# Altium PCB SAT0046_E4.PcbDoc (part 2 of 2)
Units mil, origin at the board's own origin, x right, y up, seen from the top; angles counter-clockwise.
Board outline 1588 x 1588 mil, 4 copper layers (Top Layer, GND, Inner 1, Bottom Layer); 110 components, 70 nets, 285 pads, 141 vias.
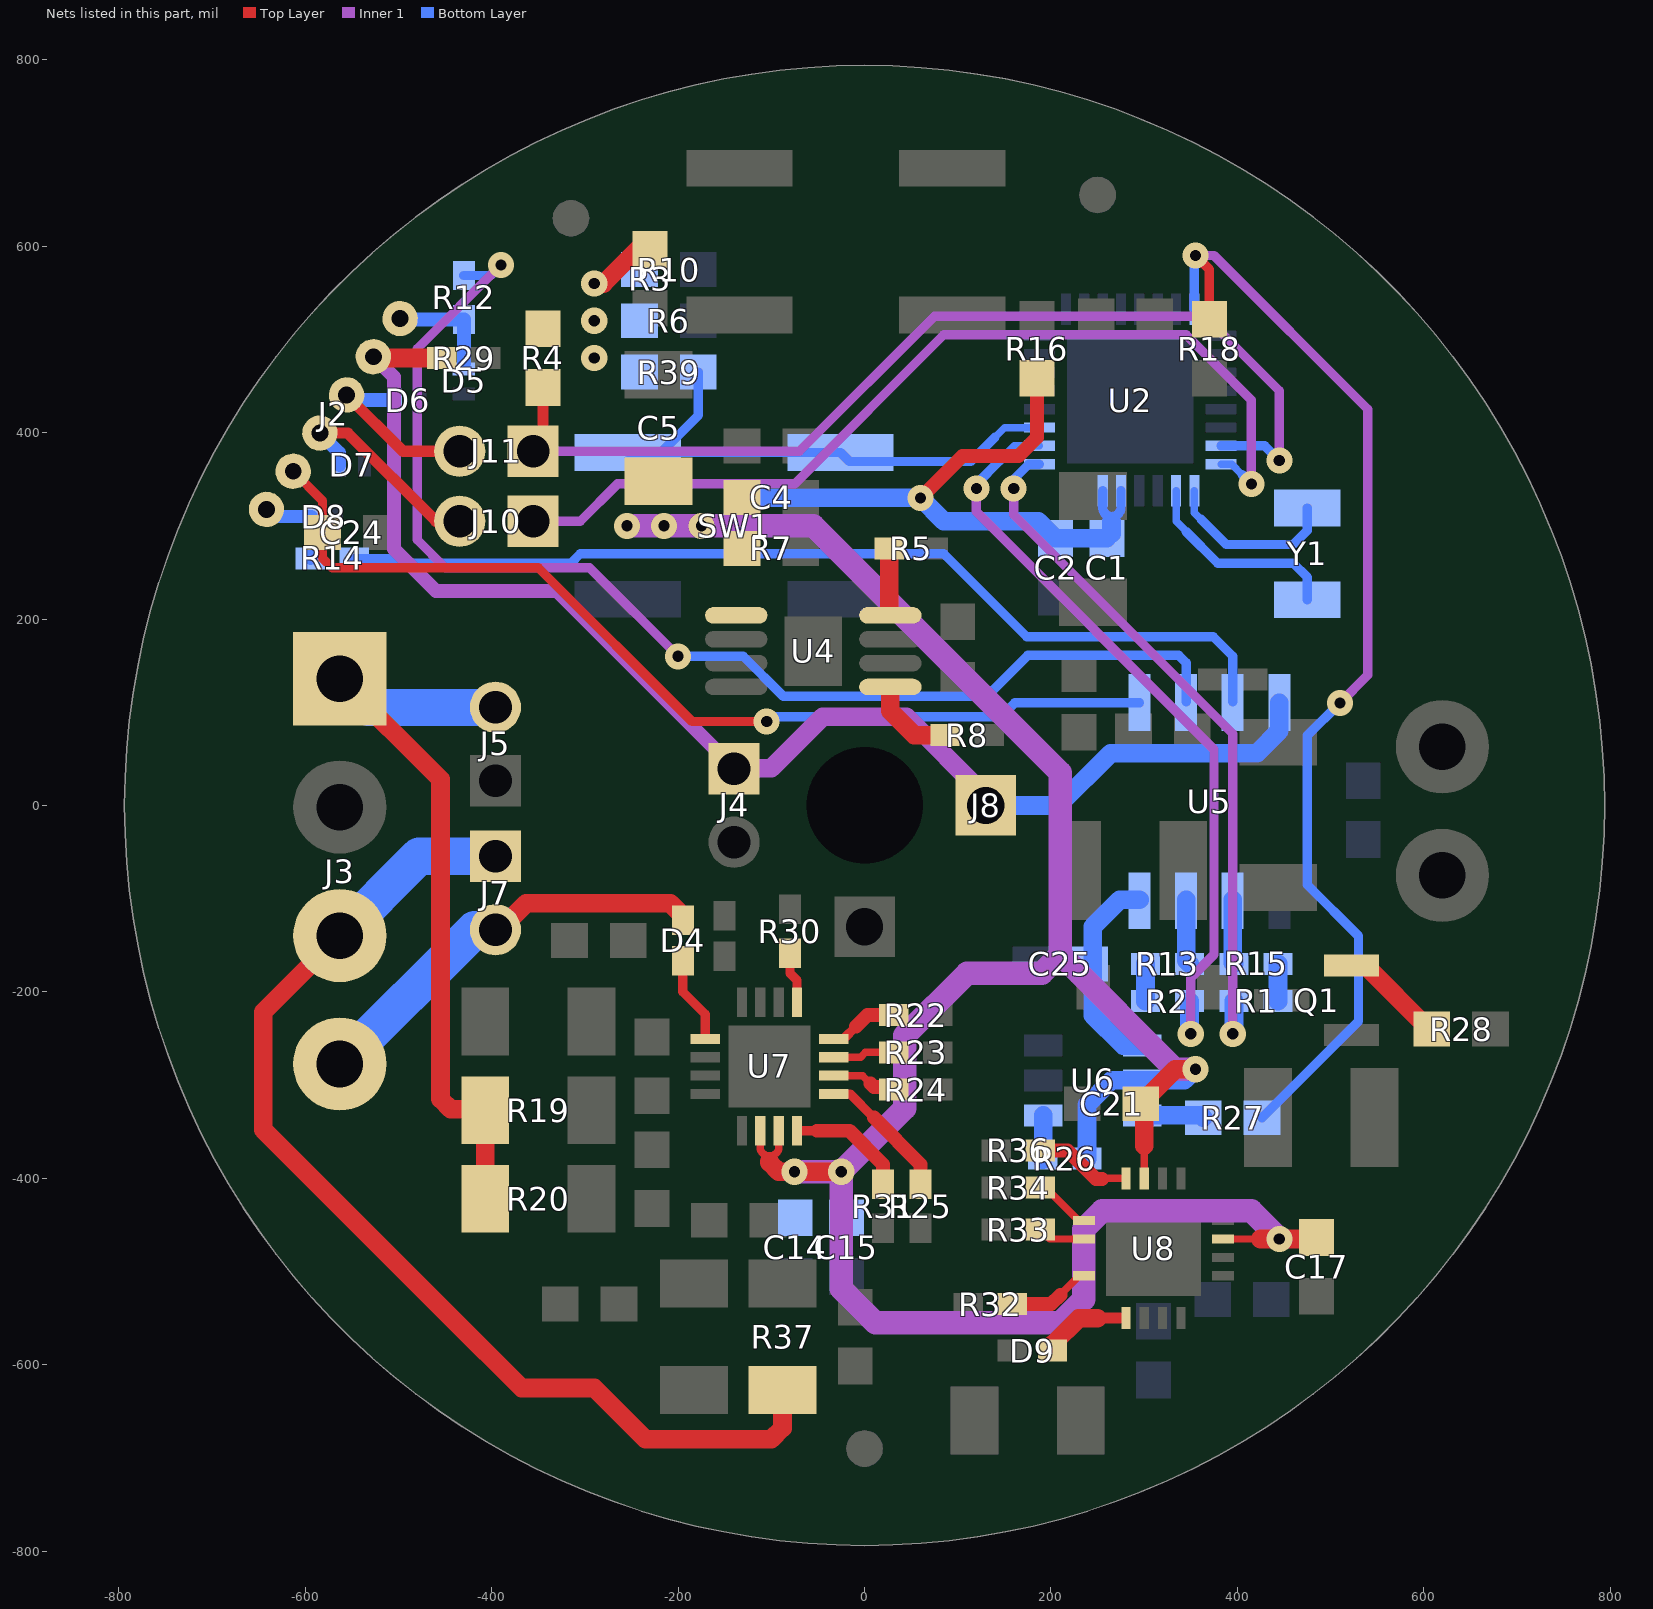
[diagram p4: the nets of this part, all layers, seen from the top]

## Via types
v1: diameter 28, hole 12, Top Layer to Bottom Layer, tented both sides, 120 vias
v2: diameter 23.62, hole 11.81, Top Layer to Bottom Layer, tented both sides, 16 vias
v3: diameter 19.68, hole 7.87, Top Layer to Bottom Layer, tented both sides, 5 vias

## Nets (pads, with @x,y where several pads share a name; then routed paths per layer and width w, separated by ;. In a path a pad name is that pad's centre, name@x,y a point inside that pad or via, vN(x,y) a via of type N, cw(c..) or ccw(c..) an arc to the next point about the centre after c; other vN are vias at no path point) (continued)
NetD4_1: D4.1 J3.4 J7.2 | length 444.9
  Top Layer w20: J7.2@-396,-133.37 -391.46,-133.37 -363.09,-105 -208.35,-105 D4.1@-195,-118.35
  Bottom Layer w40: J3.4@-563,-277.39 -562.39,-277.39 -418.37,-133.37 J7.2@-396,-133.37
NetD4_2: D4.2 U7.5 | length 97.3
  Top Layer w10: D4.2@-195,-161.65 -195,-200 -170.9,-224.1 U7.5@-170.9,-249
NetD6_1: D6.1 J2.4 J11.2 | length 194.6
  Top Layer w12: J2.4@-555.66,440.48 -495.18,380 J11.2@-434.37,380
  Bottom Layer w15: J2.4@-555.66,440.48 -550.18,435 D6.1@-509.68,435
NetD7_1: D7.1 J2.3 J10.2 | length 232.3
  Top Layer w12: J2.3@-584.34,399.52 -554.52,399.52 -460,305 J10.2@-434.37,305
  Bottom Layer w14: J2.3@-584.34,399.52 -563.39,378.57 D7.1@-563.39,365
NetD9_2: D9.2 U8.9 | length 91.8
  Top Layer w12: 250,-550 250.2,-549.8 275,-549.8
  Top Layer w20: D9.2@201.65,-585 201.65,-578.35 230,-550 250,-550
NetJ3_1: J3.1 J5.2 R19.1 R20.2 | length 822
  Top Layer w20: J3.1@-563,136 -455,28 -455,-315 -444,-326 R19.1@-408.09,-326 ; R20.2@-407.09,-422 R19.1@-407.09,-327
  Bottom Layer w40: J3.1@-563,136 -532,105 J5.2@-396,105
NetJ3_3: J3.3 J7.1 R37.1 | length 1185
  Top Layer w20: J3.3@-563,-139.59 -645,-221.59 -645,-348 -443,-550 ; -442.96,-550 -367.96,-625 -290,-625 -235,-680 -100,-680 -88,-668 R37.1@-88,-627.09
  Bottom Layer w40: J3.3@-563,-139.59 -478.04,-54.63 J7.1@-396,-54.63
NetJ10_1: J10.1 U2.24 | length 1013.8
  Inner 1 w10: J10.1@-355.63,305 -305,305 -265,345 -75,345 85,505 345,505 415,435 v1(415,345)
  Bottom Layer w8: U2.24@382.44,366.1 393.9,366.1 405,355
  Bottom Layer w10: 405,355 v1(415,345)
NetJ11_1: J11.1 R4.1 U2.23 | length 1110.8
  Top Layer w12: J11.1@-355.63,380 -345,390.63 R4.1@-345,448.5
  Inner 1 w10: J11.1@-355.63,380 -70,380 75,525 365,525 445,445 v1(445,370)
  Bottom Layer w10: U2.23@382.44,385.79 429.21,385.79 v1(445,370)
NetQ1_2: Q1.2 R28.2 | length 111.5
  Top Layer w20: Q1.2@522.4,-171.6 537.17,-171.6 R28.2@605.57,-240
NetR1_1: R1.1 U2.1 | length 762.1
  Inner 1 w10: v1(160,340) 160,312 395,77 v1(395,-245)
  Bottom Layer w10: v1(160,340) 160,350 176.1,366.1 U2.1@187.56,366.1
  Bottom Layer w20: v1(395,-245) 396.38,-243.62 R1.1@396.38,-210
NetR2_1: R2.1 U2.2 | length 826
  Inner 1 w10: v1(120,340) 120,315 375,60 375,-160 350,-185 v1(350,-245)
  Bottom Layer w8: 145,370 160.79,385.79 U2.2@187.56,385.79
  Bottom Layer w10: v1(120,340) 120,345 145,370
  Bottom Layer w20: R2.1@348.62,-210 348.62,-243.62 v1(350,-245)
NetR5_1: R5.1 U4.8 | length 65
  Top Layer w20: U4.8@26.38,210.5 R5.1@26.38,275.5
NetR8_2: R8.2 U4.5 | length 88.6
  Top Layer w20: U4.5@27.68,120.5 27.68,101.32 53.5,75.5 R8.2@86.38,75.5
NetR12_2: R12.2 U5.2 | length 1334.8
  Inner 1 w10: v1(-390,580) -480,490 -480,285 -450,255 -295,255 v1(-200,160)
  Bottom Layer w10: R12.2@-430,568.62 -401.38,568.62 v1(-390,580) ; v1(-200,160) -130,160 -87,117 131,117 175,161 337,161 345,153 U5.2@345,111.3
NetR13_1: R13.1 U5.7 | length 70.2
  Bottom Layer w20: U5.7@345,-101.3 345,-166.38 R13.1@348.62,-170
NetR14_2: R14.2 U5.3 | length 1042.9
  Bottom Layer w10: R14.2@-547.38,265 -503,265 -498,260 -315,260 -305,270 85,270 174,181 374,181 395,160 U5.3@395,111.3
NetR15_1: R15.1 U5.6 | length 69.3
  Bottom Layer w20: U5.6@395,-101.3 395,-168.62 R15.1@396.38,-170
NetR22_1: R22.1 U7.16 | length 75
  Top Layer w10: U7.16@-33.1,-250.47 -22.47,-250.47 -9,-237
  Top Layer w15: -9,-237 3,-225 R22.1@31.38,-225
NetR23_1: R23.1 U7.15 | length 66.6
  Top Layer w8: U7.15@-33.1,-270.16 -4.16,-270.16 1,-265 R23.1@31.38,-265
NetR24_1: R24.1 U7.14 | length 70.8
  Top Layer w8: U7.14@-33.1,-289.84 -2.16,-289.84 6.5,-298.5
  Top Layer w15: 6.5,-298.5 10,-302 28.38,-302 R24.1@31.38,-305
NetR25_1: R25.1 U7.13 | length 145.7
  Top Layer w10: U7.13@-33.1,-309.53 -15.47,-309.53 10,-335
  Top Layer w15: 10,-335 60,-385 R25.1@60,-406.38
NetR26_1: R26.1 U6.1 | length 47.8
  Bottom Layer w20: R26.1@191.38,-380 R26.1@191.38,-379 191.85,-378.53 U6.1@191.85,-332.4
NetR27_1: R27.1 U6.6 | length 66.4
  Bottom Layer w20: U6.6@298.15,-332.4 360.91,-332.4 R27.1@363.5,-335
NetR30_2: R30.2 U7.1 | length 55.6
  Top Layer w10: R30.2@-80,-158.62 -80,-180 -72.47,-187.53 U7.1@-72.47,-211.1
NetR31_2: R31.2 U7.12 | length 128.8
  Top Layer w10: U7.12@-72.47,-348.9 -72.37,-349 -51,-349
  Top Layer w15: -51,-349 -16,-349 20,-385 R31.2@20,-406.38
NetR32_2: R32.2 U8.8 | length 89.2
  Top Layer w8: 210,-525 230.47,-504.53 U8.8@235.2,-504.53
  Top Layer w15: R32.2@158.62,-535 200,-535 210,-525
NetR33_2: R33.2 U8.6 | length 50.8
  Top Layer w8: R33.2@188.62,-455 198.78,-465.16 U8.6@235.2,-465.16
NetR34_2: R34.2 U8.5 | length 61.3
  Top Layer w8: R34.2@188.62,-410 194.21,-410 229.68,-445.47 U8.5@235.2,-445.47
NetR36_1: R36.1 U8.4 | length 104.7
  Top Layer w8: 255,-400.65 255.46,-400.2 U8.4@280.47,-400.2
  Top Layer w15: R36.1@188.62,-370 217.81,-370 248.46,-400.65 255,-400.65
NetU2_25: U2.25 Y1.2 | length 189.1
  Bottom Layer w8: U2.25@353.9,337.56 353.9,314.1 360.93,307.07
  Bottom Layer w10: 360.93,307.07 388,280 460,280 475,295 Y1.2@475,319.21
NetU2_26: U2.26 Y1.1 | length 222.5
  Bottom Layer w8: U2.26@334.21,337.56 334.21,304.79 345,294
  Bottom Layer w10: 345,294 379,260 460,260 475,245 Y1.1@475,220.79
PC_GND: J2.5 J4.1 J8.1 R29.2 U5.4 | length 1468.3
  Top Layer w20: J2.5@-526.98,481.44 -525.55,480 R29.2@-453.62,480
  Inner 1 w15: J2.5@-526.98,481.44 -505,459.45 -505,275 -460,230 -330,230 -145,45 J4.1@-140,45
  Inner 1 w20: J4.1@-140,45 -135,40 -100,40 -45,95 45,95 130,10 J8.1@130,0
  Bottom Layer w20: J8.1@130,0 208,0 264,56 421,56 445,80 U5.4@445,110.3
UART_PC_RX: D5.1 J2.6 R12.1 | length 115.4
  Bottom Layer w15: J2.6@-498.3,522.39 -497.29,521.38 R12.1@-430,521.38 D5.1@-430,474.68
UART_PC_TX: D8.1 J2.1 R14.1 | length 97
  Bottom Layer w14: J2.1@-641.7,317.61 -634.09,310 D8.1@-593.39,310 -593.39,266.24 R14.1@-594.62,265
UART_RX: R1.2 R15.2 | length 40
  Bottom Layer w20: R1.2@443.62,-210 R15.2@443.62,-170
UART_TX: R2.2 R13.2 | length 40
  Bottom Layer w20: R2.2@301.38,-210 R13.2@301.38,-170
USR_UART_INTERRUPT: R39.1 SW1.1 SW1.4 U2.3 | length 563.6
  Bottom Layer w8: 140,395 150.47,405.47 U2.3@187.56,405.47
  Bottom Layer w10: SW1.4@-254.17,378.74 SW1.4@-218.27,378.74 ; R39.1@-178.5,465 -178.5,418.5 SW1.4@-218.27,378.74 ; 140,395 114,369 -16.09,369 SW1.1@-25.83,378.74 SW1.4@-218.27,378.74
VCC: C1.1 C2.2 C4.2 C5.1 C14.1 C15.1 C17.1 C21.1 R3.2 R4.2 R6.2 R7.2 R10.2 R16.2 R26.2 R39.2 U2.29 U2.30 U4.1 U6.5 U7.10 U7.11 U8.3 U8.15 | length 3614.2
  Top Layer w8: -111.91,-368.87 ccw(c-102,-365.55) -92.09,-368.87 ; -111.84,-368.84 U7.10@-111.84,-348.9 ; -92.16,-368.84 U7.11@-92.16,-348.9 ; 300,-365 300.16,-365.16 U8.3@300.16,-400.2 ; U8.15@384.8,-465.16 424.84,-465.16
  Top Layer w9: v1(355,-283) v1@355.16,-283.16
  Top Layer w15: v1(60,330) 105,375 165,375 185,395 R16.2@185,458.5
  Top Layer w20: v1(-290,560) -280,560 -243.5,596.5 R3.2@-230,596.5 ; -102,-382 -102,-383 -92,-393 v1(-75,-393) v1(-25,-393) ; 300,-365 300,-323.5 C21.1@296.5,-320 333.5,-283 v1(355,-283) ; 424.84,-465.16 C17.1@483.35,-465.16
  Inner 1 w25: v1(-255,300) -55,300 210,35 210,-160 190,-180 110,-180 43.19,-246.81 43.19,-324.81 v1(-25,-393) ; v1(-75,-393) v1(-25,-393) ; 212.5,-162.5 333,-283 v1(355,-283) ; v1(445,-465.16) 414.84,-435 255,-435 235.2,-454.8 235.2,-529.8 210,-555 11.65,-555 -25,-518.35 v1(-25,-393)
  Bottom Layer w10: U2.30@255.47,337.56 255.47,320.47 ccw(c265.31,319.85) 275.16,320.16 U2.29@275.16,337.56
  Bottom Layer w20: v1(-255,300) -150,300 -120,330 v1(60,330) 85,305 186.5,305 C2.2@205,286.5 C1.1@260,286.5 ; R26.2@238.62,-379 238.62,-321.38 265,-295 U6.5@298.15,-295 343,-295 v1(355,-283) ; C1.1@265,291.5 C1.1@265,305
  other v1: -215,300 -175,300 -290,480 -290,520
VCC_ISO_UART: C25.1 U5.8 U6.4 | length 223.5
  Bottom Layer w20: U5.8@295,-101.3 273.7,-101.3 245,-130 245,-225 277.6,-257.6 U6.4@298.15,-257.6
VCC_ISO_UART_EN: R18.2 R27.2 U2.16 | length 1238.7
  Top Layer w10: v1(355,590) 370,575 R18.2@370,521.5
  Inner 1 w10: v1(355,590) 375,590 540,425 540,140 v1(510,110)
  Bottom Layer w10: U2.16@353.9,532.44 353.9,588.9 v1(355,590) ; R27.2@426.5,-335 530,-231.5 530,-140 475,-85 475,75 v1(510,110)
VCC_USB: C24.1 J2.2 U5.1 | length 1063.8
  Top Layer w10: J2.2@-613.02,358.56 -581.5,327.04 -581.5,265.3 -571.2,255 -350,255 -185,90 v1(-105,90)
  Bottom Layer w10: v1(-105,90) -100,95 146,95 161.3,110.3 U5.1@295,110.3
pads on no net: FID1.1 FID2.1 FID3.1 FID4.1 FID5.1 FID6.1 H1.0 H2.0 H3.0 U2.7 U2.8 U2.11 U2.12 U2.13 U2.14 U2.18 U2.19 U2.20 U2.31 U2.32 U4.3 U4.7 U6.3

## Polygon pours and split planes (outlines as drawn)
GND on Top Layer "TOP - GND" (solid, pour order 13): -675,-379 -675,-200 -635,-160 -635,206 -491,206 -445,160 -375,160 -310,95 -310,30 -115,-165 -115,-210 -25,-210 20,-255 150,-255 180,-225 180,-55 65,-55 20,-10 -200,-10 -200,65 -365,230 -730,230 -730,205 -770,165 -770,-145 -745,-170 -745,-250 -710,-285 -710,-350 -681,-379
GND on Top Layer "TOP - GND" (solid, pour order 15): 630,425 410,425 410,585 300,695 225,695 100,570 -104,570 -204,670 -350,670 -440,580 -495,580 -495,590 -405,680 -345,680 -290,735 -195,735 -155,775 160,775 180,755 240,755 285,710 355,710 458,607 503,607 630,480
GND on Top Layer "TOP - GND" (solid, pour order 11): -305,-700 -280,-700 -270,-710 -65,-710 -40,-735 25,-735 50,-710 50,-655 30,-635 30,-565 50,-545 155,-545 195,-585 195,-650 395,-650 325,-720 250,-720 210,-760 -200,-760 -230,-730 -275,-730
GND on Bottom Layer "BOTTOM - GND" (solid, pour order 17): -735,230 -365,230 -289,154 -244,154 -200,110 -200,-10 15,-10 60,-55 225,-55 225,-105 200,-130 160,-130 150,-140 150,-155 0,-305 0,-610 40,-610 40,-635 75,-635 75,-715 340,-715 340,-725 305,-725 275,-755 -205,-755 -230,-730 -295,-730 -355,-670 -415,-670 -660,-425 -660,-370 -720,-310 -720,-245 -760,-205 -760,155 -755,160 -635,160 -635,-310 -595,-350 -535,-350 -310,-125 -310,95 -375,160 -445,160 -491,206 -635,206 -635,160 -755,160 -735,180
GND on Bottom Layer "BOTTOM - GND" (solid, pour order 19): -475,615 -390,615 -335,670 -290,670 -235,615 -110,615 -25,530 60,530 225,695 275,695 310,660 405,660 515,550 520,550 520,570 415,675 380,675 335,720 250,720 205,765 -200,765 -235,730 -310,730 -375,665 -425,665
GND on GND (split plane): 209 vertices, not listed, extent -768.98,-768.98 768.98,768.98

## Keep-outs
Keep-Out Layer:
  text ".Layer_Name" at -1723,-2658.49 h60

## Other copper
Top Layer:
  region net GND: -258,495 -115,495 -60,440 -60,420 -95,420 -105,410 -105,365 -155,365 -155,400 -185,430 -258,430
  region net NetC23_1: 670,85 670,30 650,10 435,10 400,45 400,150 430,150 495,85 565,85 595,115 640,115
  region net LOOP_PWR: 265,-220 265,40 280,55 305,55 310,60 310,100 202,100 202,-197 225,-220
  region net LOOP-: 375,100 330,100 330,60 305,35 285,35 285,-110 315,-140 625,-140 670,-95 670,-40 650,-20 435,-20 375,40
  region net GND: 750,-160 750,-90 770,-70 770,180 730,220 730,290 680,340 680,400 650,400 625,425 520,425 520,365 445,290 445,195 495,145 635,145 685,95 685,-160
  region net VCC: -110,196 -211,196 -310,295 -310,475 -321,486 -364,486 -364,531 -320,575 -270,575 -270,397 -248,375 -170,375 -170,350 -110,350
  region net NetC3_1: 117,63 149,63 207,121 390,121 390,175 277,288 57,288 57,262 95,262 131,226 131,102 117,88
  region net VCC: -112,-382 -112,-373 -92,-373 -92,-382
  region net NetD2_2: 356,-221 477,-221 477,-153 374,-153 356,-171
  region net GND: -433,-269 -346,-269 -346,-191 -433,-191
  region net GND: -267.09,-383 -354.09,-383 -354.09,-461 -267.09,-461
  text ".Layer_Name" at -1723,-2658.49 h60
Inner 1:
  text ".Layer_Name" at -1722,-2659.49 h60
Bottom Layer:
  region net GND: 10,180 32,202 32,241 -83,241 -83,180
  region net LOOP-: 515,-16 515,-58 584,-127 640,-127 670,-97 670,-50 636,-16
  region net GND: 660,-390 660,-230 750,-140 750,140 645,245 645,395 650,395 720,325 720,240 765,195 765,-185 735,-215 735,-290 710,-315 710,-340
  region net VCC: 255,305 255,310 275,310 275,305
  region net NetC23_1: 515,47 583,115 640,115 670,85 670,40 635,5 515,5
  region net VCC: -221,594 -276,594 -304,566 -304,474 -276,446 -221,446
  region net GND: 295,299 295,306 315,306 315,299
  region net VCC: -99.4,-463.98 -99.4,-394.4 -85,-380 -15,-380 0.6,-395.6 0.6,-463.98
  text ".Layer_Name" at -1723,-2658.49 h60
GND (plane layer: these items are gaps in the copper):
  text ".Layer_Name" at -1721,-2658.49 h60

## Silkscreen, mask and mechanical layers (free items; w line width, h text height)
Top Overlay:
  circle w10: c-290,305 r5
  circle w10: c-290,380 r5
  text "SAT0046" at 315,279 h45
  text "Rev. E3" at 315,239 h45
  text "TempTx1EVM" at 315,199 h45
  text "Loop +" at 560,155 h30
  text "(24V)" at 655,155 h30
  text "PC_GND" at 70,-110 h30
  text "Loop -" at 560,-180 h30
  text "(GND)" at 650,-180 h30
  text "GND" at 65,-185 h30
  text ".Layer_Name" at -1723,-2658.49 h60
Bottom Overlay:
  text "of J3 (pins 1 and 4 are for IDAC)" at -285,-641 h30 r270
  text "Install 4 wire RTD between pins 1,2,3,4" at -255,-641 h30 r270
  text "Install 3 wire RTD between pins 1,2,3 of J3 (pin 1 is the ref)" at -226,-641 h30 r270
  text "Install 2 wire RTD between pins 2 and 3 of J3" at -196,-641 h30 r270
  text "J7 closed for 2 and 3 wire RTD" at -166,-641 h30 r270
  text "J5 closed for 2 wire RTD" at -136,-641 h30 r270
  text ".Layer_Name" at -1723,-2658.49 h60
Top Paste:
  text ".Layer_Name" at -1723,-2658.49 h60
Bottom Paste:
  text ".Layer_Name" at -1723,-2658.49 h60
Top Solder:
  lines w40: 0,-773.85 cw(c0.15,0.38) -0.02,774.6 ; 0.02,-773.6 ccw(c-0.15,0.62) 0,774.85
  text ".Layer_Name" at -1723,-2658.49 h60
  text ".Layer_Name" at -1723,-2658.49 h60
Bottom Solder:
  lines w40: 0,-773.85 cw(c0.15,0.38) -0.02,774.6 ; 0.02,-773.6 ccw(c-0.15,0.62) 0,774.85
  text ".Layer_Name" at -1723,-2658.49 h60
Drill Guide:
  text ".Layer_Name" at -1723,-2658.49 h60
M1 Board Outline:
  circle w10: c0,0 r794
  text ".Layer_Name" at -1723,-2658.49 h60
M2 Board Dimensions:
  rectangle: -2300.5,-2085.5 -2175.5,-1960.5
  rectangle: -2175.5,-2210.5 -1800.5,-2085.5
  lines w7: -2300.5,-2085.5 -1300.5,-2085.5 ; -2175.5,-2210.5 -2175.5,-1960.5 ; -2050.5,-2210.5 -2050.5,-1960.5 ; -1800.5,-2210.5 -1800.5,-1960.5 ; -1550.5,-2210.5 -1550.5,-1960.5 ; -2300.5,-2210.5 -1300.5,-2210.5 -1300.5,-1960.5 -2300.5,-1960.5 -2300.5,-2210.5
  lines w10: -2300.5,-2275.5 -2300.5,-2255.5 ; -2240.5,-2285.5 -2300.5,-2265.5 ; -2240.5,-2245.5 -2300.5,-2265.5 ; -2076.42,-2265.5 -2300.5,-2265.5 ; -1524.58,-2265.5 -1300.5,-2265.5 ; -1360.5,-2285.5 -1300.5,-2265.5 ; -1360.5,-2245.5 -1300.5,-2265.5 ; -1300.5,-2275.5 -1300.5,-2255.5
  text "1000 (mil)" at -2066.42,-2301.49 h60
  text ".Layer_Name" at -1723,-2658.49 h60
M3 3D STEP Top:
  text ".Layer_Name" at -1723,-2658.49 h60
M4 3D STEP Bottom:
  text ".Layer_Name" at -1723,-2658.49 h60
M5 Assembly Top:
  lines w7: 2839,-1689.5 3964,-1689.5 ; 2839,-1567 3961.5,-1567 ; 3154,-1809.5 3154,-1447 ; 3539,-1809.5 2839,-1809.5 ; 3539,-1447 2839,-1447 ; 2839,-1809.5 3964,-1809.5 3964,-1447 2839,-1447 ; 2839,-1809.5 2839,-1447
  lines w10: -2592,-2730.17 4008,-2730.17 ; -2592,-2526.83 4010,-2526.83 ; -2592,-2323.5 -2592,-2933.5 1413,-2933.5 4010,-2933.5 4010,-2323.5 -2591.5,-2323.5 -2591.5,-2933.5 -1016,-2933.5 ; -127,-2933.5 -127,-2323.5 ; 1140,-2526.83 1140,-2323.5 ; 1980,-2526.83 1980,-2323.5 ; 2602,-2940 2602,-2737.17
  text "TABLE 1" at 3226.5,-1412 h40
  text "Variant" at 2864,-1522 h40
  text "Label text" at 3299,-1522 h40
  text "001" at 2931.5,-1642 h40
  text "ChangeMe!" at 3209,-1644.5 h40
  text "002" at 2931.5,-1767 h40
  text "ChangeMe!" at 3204,-1769.5 h40
  text "COMPONENTS MARKED 'DNP' SHOULD NOT BE POPULATED." at -1146.5,-2118.5 h60
  text "ASSEMBLY VARIANT:" at -1147,-2234 h60
  text ".VariantName" at -111,-2234 h60
  text "PCB VIEWED FROM TOP SIDE" at -2528.5,-2455.67 h60
  text "BOARD #:" at -52,-2455.67 h60
  text ".PRJ_Number" at 493.5,-2455.67 h60
  text "REV:" at 1338,-2455.67 h60
  text ".PCB_Rev" at 1629.5,-2455.67 h60
  text "SVN REV:" at 2176,-2455.67 h60
  text ".VersionControl_RevNumber" at 2682,-2455.67 h60
  text "IGNORE ->" at -2528.5,-2658.49 h60
  text "PLOT NAME =" at -2528.5,-2864.34 h60
  text ".plot_File_Name" at -1723,-2864.34 h60
  text "GENERATED    :" at -50,-2864.34 h60
  text ".Print_Date" at 819.5,-2864.34 h60
  text ".Print_Time" at 1548.5,-2864.34 h60
  text "TEXAS INSTRUMENTS" at 2813,-2864.34 h60
M6 Assembly Bottom:
  lines w10: -2592.5,-2527.33 4009.5,-2527.33 ; -2590.5,-2730.67 4009.5,-2730.67 ; -1184.5,-2940.5 -1184.5,-2737.67 ; -562.5,-2527.33 -562.5,-2324 ; 277.5,-2527.33 277.5,-2324 ; 1544.5,-2934 1544.5,-2324 ; 2433.5,-2934 4009,-2934 4009,-2324 -2592.5,-2324 -2592.5,-2934 4.5,-2934 4009.5,-2934 4009.5,-2324
  text "COMPONENTS MARKED 'DNP' SHOULD NOT BE POPULATED." at 3802,-2118 h60
  text ".VariantName" at 2758,-2234 h60
  text "ASSEMBLY VARIANT:" at 3797,-2234 h60
  text ".VersionControl_RevNumber" at -1264.5,-2456.17 h60
  text "SVN REV:" at -758.5,-2456.17 h60
  text ".PCB_Rev" at -212,-2456.17 h60
  text "REV:" at 79.5,-2456.17 h60
  text ".PRJ_Number" at 924,-2456.17 h60
  text "BOARD #:" at 1469.5,-2456.17 h60
  text "PCB VIEWED FROM BOTTOM SIDE" at 3946,-2456.17 h60
  text "IGNORE ->" at 247.85,-2658.49 h60
  text "TEXAS INSTRUMENTS" at -1395.5,-2864.84 h60
  text ".Print_Time" at -131,-2864.84 h60
  text ".Print_Date" at 598,-2864.84 h60
  text "GENERATED    :" at 1467.5,-2864.84 h60
  text ".plot_File_Name" at 3140.5,-2864.84 h60
  text "PLOT NAME =" at 3946,-2864.84 h60
M9 Title Sheet:
  drawing of 57 lines, arcs and shapes, not listed
  text "1" at -1560.16,6236.5 h70
  text "2" at 935.5,6236.5 h70
  text "3" at 3424.84,6236.5 h70
  text "4" at 5931.51,6236.5 h70
  text "5" at 8430.5,6236.5 h70
  text "6" at 10935.5,6236.5 h70
  text "A" at -2716.5,5093.5 h70
  text "A" at 12083.5,5093.5 h70
  text "B" at -2716.5,2713.5 h70
  text "B" at 12083.5,2713.5 h70
  text "C" at -2716.5,338.5 h70
  text "C" at 12083.5,338.5 h70
  text "PROJECT TITLE:" at 9043.5,-1522.5 h45
  text ".PRJ_Title" at 9093.5,-1655.83 h70
  text "DESIGNED FOR:" at 9043.5,-1823.5 h45
  text ".PRJ_Customer" at 9093.5,-1963.5 h70
  text "D" at -2716.5,-2031.5 h70
  text "D" at 12083.5,-2031.5 h70
  text "FILE NAME:" at 9043.5,-2123.5 h45
  text ".PCB_File_Name_No_Path" at 9093.5,-2243.5 h70
  text "Texas Instruments (TI) and/or its licensors do not warrant the accuracy or completeness of this specification" at 4074,-2405.34 h45
  text "ENGINEER:" at 9043.5,-2413.5 h45
  text "LAYOUT BY:" at 10548.5,-2413.5 h45
  text "or any information contained therein. TI and/or its licensors do not warrant that this design will meet" at 4029.01,-2518 h45
  text ".PRJ_Engineer" at 9093.5,-2568.49 h70
  text ".PCB_Layout" at 10599,-2568.49 h70
  text "the specifications, will be suitable for your application or fit for any particular purpose, or will operate in" at 4029.01,-2630.67 h45
  text ".Layer_Name" at -1723,-2658.49 h60
  text "ALTIUM DESIGNER VERSION:" at 10548.5,-2723.5 h45
  text "an implementation. TI and/or its licensors do not warrant that the design is production worthy. You should" at 4029.01,-2743.33 h45
  text "completely validate and test your design implementation to confirm the system functionality for your application." at 4074,-2856 h45
  text ".print_Scale" at 9093.5,-2856.83 h70
  text ".Application_BuildNumber" at 10599,-2856.83 h70
  text "1" at -1560.16,-3063.5 h70
  text "2" at 935.5,-3063.5 h70
  text "3" at 3424.84,-3063.5 h70
  text "4" at 5931.51,-3063.5 h70
  text "5" at 8430.5,-3063.5 h70
  text "6" at 10935.5,-3063.5 h70
M10 Fab Notes:
  drawing of 206 lines, arcs and shapes, not listed
  text "DESIGN INFORMATION" at 10081.02,5010 h60
  text "(REFER ALSO ARRAY/PANEL PROFILING INFORMATION)" at 9719.46,4848.29 h60
  text "BOARD SIZE" at 9033.46,4844 h60
  text "1588 MILS DIA." at 9960,4730 h60
  text "Number of Layers :" at 9436.46,4519 h60
  text "4" at 10531.27,4509 h60
  text "MIN. TRACK WIDTH:" at 9436.46,4380 h60
  text "6" at 10532.7,4380 h60
  text "MIL" at 10687.46,4380 h60
  text "MIN. CLEARANCE:" at 9436.46,4248 h60
  text "10" at 10532.7,4248 h60
  text "MIL" at 10687.46,4248 h60
  text "MIN. VIA PAD SIZE:" at 9436.46,4116 h60
  text "28" at 10502.71,4116 h60
  text "MIL" at 10687.46,4116 h60
  text "0.05mm (2MIL)" at 10131.46,3974.29 h60
  text "MINIMUM ANNULAR RING" at 9107.23,3970 h60
  text "EXTERNAL" at 10839.46,3970 h60
  text "PER" at 9307.23,3852 h60
  text "IPC-D-275 CLASS 2 LEVEL C" at 9527.23,3852 h60
  text "MIL, HOLES" at 11015.46,3739.71 h60
  text "+/-" at 10623,3739 h60
  text "+/-" at 11477,3739 h60
  text "REGISTRATION TOLERANCES:" at 9107.23,3734 h60
  text "METAL" at 10307,3734 h60
  text "5" at 10883.2,3734 h60
  text "3" at 11716.2,3734 h60
  text "MIL" at 11832.46,3734 h60
  text "MATERIAL:" at 9032.46,3524.54 h60
  text "FR-4 High Tg" at 10018.9,3384.21 h60
  text "FR-4" at 9493.46,3375.64 h60
  text "X" at 9865.46,3375.64 h60
  text "OTHER" at 10941.46,3375.64 h60
  text "44 MIL (1.1mm) +/-10%" at 9773.56,3212.92 h60
  text "THICKNESS:" at 9107.23,3208.64 h60
  text "X" at 9645.4,3208.64 h60
  text "OTHER" at 11058.46,3208.64 h60
  text "TOLERANCE:" at 9107.23,3050.64 h60
  text "X" at 9946.53,3050.64 h60
  text "ANSI IPC-6012 TYPE 3 CLASS 2" at 10133.48,3050.64 h60
  text "OTHER +/-" at 10133.46,2894.64 h60
  text "BOW & TWIST:" at 9107.23,2737.64 h60
  text "X" at 9946.53,2737.64 h60
  text "ANSI IPC-6012 TYPE 3 CLASS 2" at 10133.48,2737.64 h60
  text "OTHER +/-" at 10133.46,2579.13 h60
  text "COPPER THICKNESS (FINISHED):" at 9032.46,2443.64 h60
  text "1.4MIL (1oz)" at 9912.46,2290.92 h60
  text "2MIL (1.4oz)" at 10679.46,2290.92 h60
  text "2.8MIL (2oz)" at 11406.46,2290.92 h60
  text "OUTER:" at 9389.46,2286.64 h60
  text "X" at 9784,2286 h60
  text "1.4MIL (1oz)" at 9912.46,2133.92 h60
  text "2.8MIL (2oz)" at 10679.46,2133.92 h60
  text "N/A" at 11406,2134.29 h60
  text "INNER SIGNAL:" at 9100.38,2129.64 h60
  text "X" at 9785.42,2129.64 h60
  text "DRILLING:" at 9032.46,1990.64 h60
  text "REFERENCE:" at 9107.23,1873.64 h60
  text "X" at 9755.46,1873.64 h60
  text "AS SHOWN" at 9942.46,1873.64 h60
  text "X" at 10656.46,1873.64 h60
  text "NC_DRILL FILES" at 10793.46,1873.64 h60
  text "PTH MIN COPPER THICKNESS:" at 9107.23,1715.64 h60
  text "X" at 10457.46,1715.64 h60
  text "1MIL" at 10594.46,1715.64 h60
  text "OTHER" at 11091.46,1715.64 h60
  text "BOARD FINISH:" at 9032.46,1556.64 h60
  text "SILKSCREEN:" at 9187.68,1438.64 h60
  text "X" at 10136.46,1438.64 h60
  text "TOP" at 10262.46,1438.64 h60
  text "X" at 10646.46,1438.64 h60
  text "BOTTOM" at 10773.46,1438.64 h60
  text "SILKSCREEN COLOR:" at 9187.68,1271.64 h60
  text "X" at 10135.42,1271.64 h60
  text "WHITE" at 10262.46,1271.64 h60
  text "OTHER" at 10773.46,1271.64 h60
  text "SOLDER RESIST COLOR:" at 9187.68,1101.64 h60
  text "GREEN" at 9882.46,942.44 h60
  text "BLUE" at 10473.46,942.44 h60
  text "OTHER" at 11011.46,942.44 h60
  text "X" at 10860,940 h60
  text "BLACK" at 11510,940 h60
  text "IMMERSION GOLD (ENIG)" at 10093.46,753.92 h60
  text "SURFACE FINISH:" at 9032.46,749.64 h60
  text "X" at 9906.51,749.64 h60
  text "IMM. TIN/SILVER OR EQUIV" at 9362,592.64 h60
  text "OTHER" at 10793.46,592.64 h60
  text "ARRAY/PANEL:" at 9032.46,413.64 h60
  text "CUT AND TRIM PER MECH LAYER 1" at 10093.46,409.35 h60
  text "N.C. ROUTE" at 10093.46,257.64 h60
  text "X" at 10772.46,257.64 h60
  text "V. SCORE" at 10959.46,257.64 h60
  text "CERTIFICATION:" at 9032.46,120.64 h60
  text "MATERIALS AND WORKMANSHIP FOR ALL PCBS" at 9757.46,120.64 h60
  text "TO MEET OR EXCEED THE REQUIREMENTS OF:" at 9757.46,22.64 h60
  text "X" at 9383.96,-113.87 h60
  text "ANSI IPC-A-600F CLASS ->" at 9522.96,-113.87 h60
  text "X" at 11162.02,-113.87 h60
  text "2" at 11280.96,-113.86 h60
  text "1" at 10965.96,-115.36 h60
  text "3" at 11634.96,-115.36 h60
  text "X" at 9386.02,-273.36 h60
  text "UL 94V-0" at 9522.96,-273.36 h60
  text "X" at 10198.02,-273.36 h60
  text "RoHS" at 10334.96,-273.36 h60
  text "OTHER" at 10979.36,-273.36 h60
  text "PER ORDER" at 11376.42,-273.36 h60
  text "ADDITIONAL REQUIREMENTS:" at 9032.46,-414.36 h60
  text "MICROSECTION:" at 9107.23,-529.36 h60
  text "YES" at 10012.96,-529.36 h60
  text "REQUIRED" at 10874.46,-685.51 h60
  text "BARE BOARD ELEC. TEST:" at 9107.23,-688.36 h60
  text "NONE" at 10412.96,-688.36 h60
  text "X" at 10747.46,-688.36 h60
  text "PER ORDER" at 11466.46,-688.36 h60
  text "MANUFACTURER'S ID/LOGO:" at 9107.23,-845.36 h60
  text "RAIL" at 10572.96,-849.65 h60
  text "METAL" at 11064.77,-849.65 h60
  text "X" at 11440,-850 h60
  text "SILK" at 11576.46,-849.65 h60
  text ".Layer_Name" at -1723,-2658.49 h60
M11 Gerber Information:
  lines w10: -2592,-2730.17 4008,-2730.17 ; -2592,-2526.83 4010,-2526.83 ; -2592,-2323.5 -2592,-2933.5 1413,-2933.5 4010,-2933.5 4010,-2323.5 -2591.5,-2323.5 -2591.5,-2933.5 -1016,-2933.5 ; -127,-2933.5 -127,-2323.5 ; 1140,-2526.83 1140,-2323.5 ; 1980,-2526.83 1980,-2323.5 ; 2602,-2940 2602,-2737.17
  text "ALL ARTWORK VIEWED FROM TOP SIDE" at -2528.5,-2455.67 h60
  text "BOARD #:" at -52,-2455.67 h60
  text ".PRJ_Number" at 493.5,-2455.67 h60
  text "REV:" at 1338,-2455.67 h60
  text ".PCB_Rev" at 1629.5,-2455.67 h60
  text "SVN REV:" at 2176,-2455.67 h60
  text ".VersionControl_RevNumber" at 2682,-2455.67 h60
  text "LAYER NAME =" at -2528.5,-2658.49 h60
  text "PLOT NAME =" at -2528.5,-2864.34 h60
  text ".plot_File_Name" at -1723,-2864.34 h60
  text "GENERATED    :" at -50,-2864.34 h60
  text ".Print_Date" at 819.5,-2864.34 h60
  text ".Print_Time" at 1548.5,-2864.34 h60
  text "TEXAS INSTRUMENTS" at 2813,-2864.34 h60
M12 Stackup:
  lines w6: 7265,5903 11940,5903 ; 7265,6019.7 11940,6019.7 ; 7205,5173 ccw(c7243,5173) 7243,5135 11962,5135 ccw(c11962,5173) 12000,5173 12000,6117 ccw(c11962,6117) 11962,6155 7243,6155 ccw(c7243,6117) 7205,6117 7205,5173
  text "Layer Stack Up Detail for: SAT0046_E1.PcbDoc" at 7265,6048.75 h52
  text "Layer" at 7265,5976.2 h27
  text "Gerber" at 8207.96,5976.2 h27
  text "Copper" at 8784.23,5976.2 h27
  text "Dielectric" at 9404.6,5976.2 h27
  text "Dielectric" at 10043.85,5976.2 h27
  text "Dielectric" at 10796.87,5976.2 h27
  text "Dielectric" at 11436.13,5976.2 h27
  text "Name" at 7265,5922.2 h27
  text "Document" at 8207.96,5922.2 h27
  text "Thickness" at 8784.23,5922.2 h27
  text "Height" at 9404.6,5922.2 h27
  text "Material" at 10043.85,5922.2 h27
  text "Constant" at 10796.87,5922.2 h27
  text "Type" at 11436.13,5922.2 h27
  text "Top Solder Mask" at 7265,5846.88 h38
  text "(.GTS)" at 8207.96,5846.88 h38
  text "0.4mil" at 9404.6,5846.88 h38
  text "Solder Resist" at 10043.85,5846.88 h38
  text "3.50" at 10796.87,5846.88 h38
  text "Top Layer" at 7265,5740.62 h38
  text "(.GTL)" at 8207.96,5740.62 h38
  text "1.4mil" at 8784.23,5740.62 h38
  text "12.6mil" at 9404.6,5687.5 h38
  text "370HR" at 10043.85,5687.5 h38
  text "4.80" at 10796.87,5687.5 h38
  text "Core" at 11436.13,5687.5 h38
  text "GND" at 7265,5634.38 h38
  text "(.GP1)" at 8207.96,5634.38 h38
  text "1.4mil" at 8784.23,5634.38 h38
  text "12.6mil" at 9404.6,5581.25 h38
  text "370HR" at 10043.85,5581.25 h38
  text "4.80" at 10796.87,5581.25 h38
  text "PrePreg" at 11436.13,5581.25 h38
  text "Inner 1" at 7265,5528.12 h38
  text "(.G1)" at 8207.96,5528.12 h38
  text "1.4mil" at 8784.23,5528.12 h38
  text "12.6mil" at 9404.6,5475 h38
  text "370HR" at 10043.85,5475 h38
  text "4.80" at 10796.87,5475 h38
  text "Core" at 11436.13,5475 h38
  text "Bottom Layer" at 7265,5421.88 h38
  text "(.GBL)" at 8207.96,5421.88 h38
  text "1.4mil" at 8784.23,5421.88 h38
  text "Bottom Solder Mask" at 7265,5315.62 h38
  text "(.GBS)" at 8207.96,5315.62 h38
  text "0.4mil" at 9404.6,5315.62 h38
  text "Solder Resist" at 10043.85,5315.62 h38
  text "3.50" at 10796.87,5315.62 h38
  text ".Layer_Name" at -1723,-2658.49 h60
M13 Component Bodies Top:
  text ".Layer_Name" at -1723,-2658.49 h60
M14 Component Bodies Bottom:
  text ".Layer_Name" at -1723,-2658.49 h60
M15 Courtyards Top:
  text ".Layer_Name" at -1723,-2658.49 h60
M16 Courtyards Bottom:
  text ".Layer_Name" at -1723,-2658.49 h60
Drill Drawing:
  text ".legend" at 4935,3640 h60
  text "Drill Table" at 4935,3455 h60
  text ".Layer_Name" at -1723,-2658.49 h60

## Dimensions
0,-794 to 0,794 on M2 Board Dimensions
